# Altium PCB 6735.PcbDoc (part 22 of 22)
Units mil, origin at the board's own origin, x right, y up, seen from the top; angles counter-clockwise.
Board outline 2641.73 x 5165.35 mil, 6 copper layers (Top, Inner Layer 2, Inner Layer 3, Inner Layer 4, Inner Layer 5, Bottom), stack 35.7 mil thick; 1011 components, 790 nets, 4118 pads, 9325 vias.
Unrouted connection lines stored in the file: 4610.
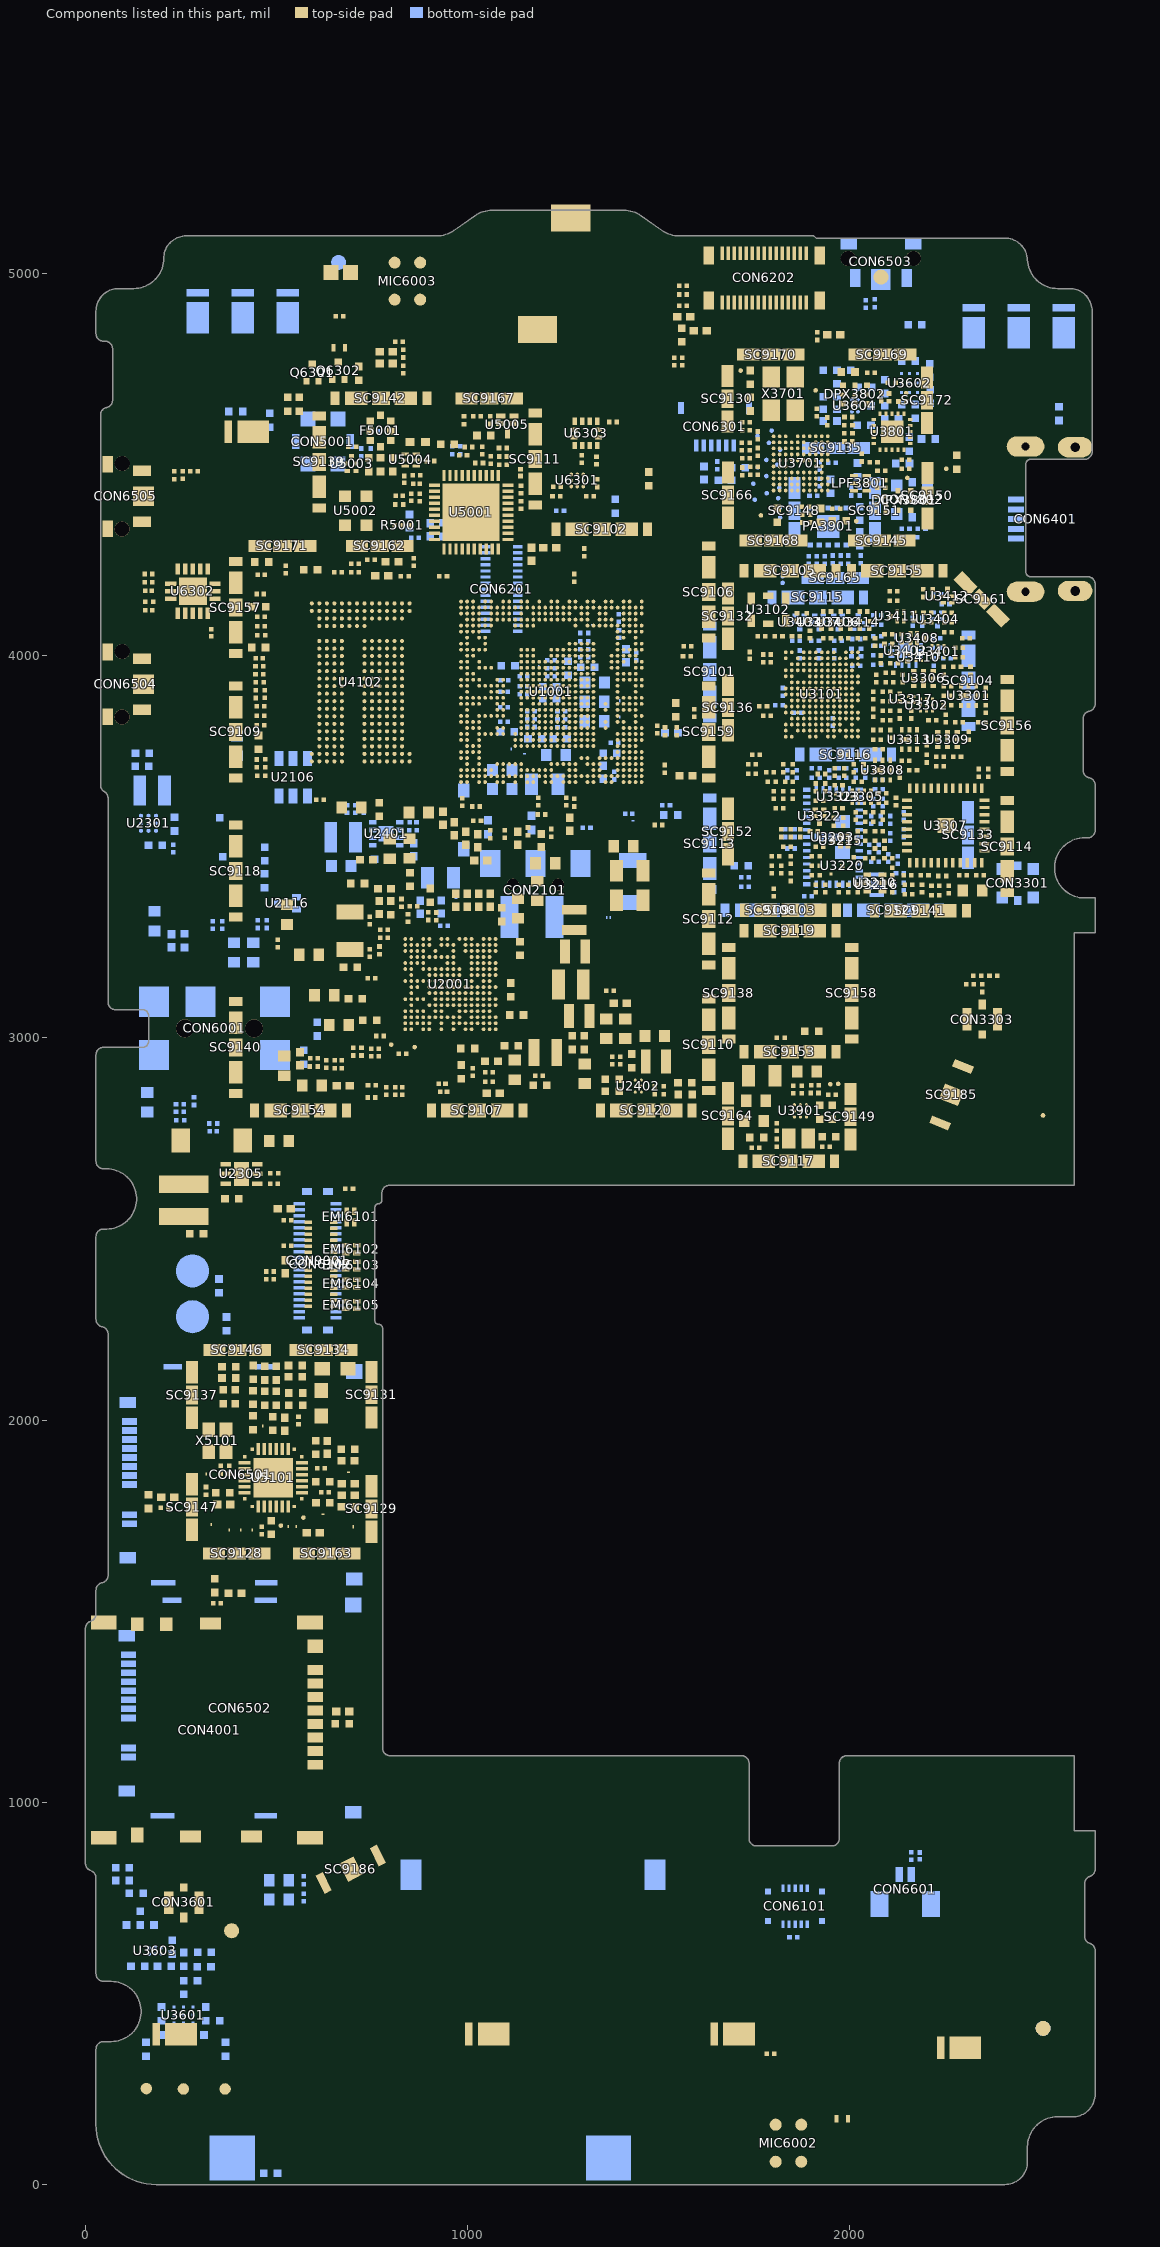
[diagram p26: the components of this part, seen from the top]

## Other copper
Top:
  region net VPA_PMU: 1219.95,2964.49 1283.95,2964.49 1283.95,2922.49 1219.95,2922.49 1219.95,2964.49
  region net D_GND: 1193.95,4655.49 592.95,4655.49 592.95,4691.49 1193.95,4691.49 1193.95,4655.49
  region net VBAT: 1344.95,3020.83 1423.05,3020.83 1440.31,3038.09 1440.31,3070.19 1441.95,3071.83 1449.95,3071.83 1449.95,3022.83 1425.45,2998.33 1344.95,2998.33 1344.95,3020.83
  region net VPROC_PMU: 1302.31,3174.09 1314.31,3174.09 1327.31,3187.09 1327.31,3311.09 1338.56,3322.34 1343.31,3322.34 1343.31,3167.09 1302.31,3167.09 1302.31,3174.09
  region net VBAT_VPROC: 1047.95,3111.83 1049.75,3111.83 1057.95,3104.83 1126.95,3104.83 1129.95,3107.83 1129.95,3119.83 1126.69,3123.09 1095.08,3123.09 1092.82,3121.83 1047.95,3121.83 1047.95,3111.83
  region net D_GND: 2218.65,4803.08 2218.65,4771.49 1694.95,4771.49 1694.95,4316.49 2186.95,4316.49 2186.95,4771.28 2218.95,4771.28 2218.95,4284.49 1664.95,4284.49 1664.95,4803.08 2218.65,4803.08
  region net D_GND: 765.95,2199.49 765.95,2167.49 294.95,2167.49 294.95,1667.49 732.95,1667.49 732.95,2163.49 763.95,2163.49 763.95,1635.49 262.95,1635.49 262.95,2199.49 765.95,2199.49
  region net VBAT_RF: 2302.65,3470.59 2330.65,3470.59 2330.65,3428.59 2302.65,3428.59 2302.65,3470.59
  region net D_GND: 2007.95,2981.56 2007.95,2943.96 1701.95,2943.96 1701.95,2694.96 1985.95,2694.96 1985.95,2940.96 2021.95,2940.96 2021.95,2658.96 1664.95,2658.96 1664.95,2981.56 2007.95,2981.56
  region net D_GND: 1043.08,3854.49 1043.08,3871.49 1049.08,3877.49 1061.95,3877.49 1063.95,3875.49 1063.95,3854.49 1043.08,3854.49
  region net N18393681: 1764.31,2786.56 1833.31,2786.56 1840.31,2793.56 1853.31,2780.56 1843.31,2770.56 1801.81,2770.56 1784.31,2753.06 1784.31,2740.56 1764.31,2740.56 1764.31,2786.56
  region net D_GND: 1100.45,4007.99 1108.95,4016.49 1129.95,4016.49 1134.95,4011.49 1211.95,4011.49 1227.95,4027.49 1241.58,4027.49 1252.33,4038.24 1252.33,4038.49 1257.33,4043.49 1345.58,4043.49 1353.76,4035.3 1359.31,4030.49 1380.95,4030.49 1380.95,4064.49 1378.95,4066.49 1277.95,4066.49 1277.35,4067.09 1143.55,4067.09 1117.55,4041.09 1064.69,4041.09 1087.48,4020.96 1100.45,4007.99
  region net D_GND: 1037.23,3701.49 1044.16,3701.49 1071.16,3728.49 1112.33,3728.49 1116.95,3733.11 1116.95,3765.49 1113.33,3769.11 1059.08,3769.11 1055.08,3765.11 1055.08,3764.62 1041.95,3751.49 1041.95,3711.32 1035,3704.37 1037.23,3701.49
  region net VPA_PMU: 1541.31,2931.09 1569.4,2931.09 1569.4,2904.09 1569.31,2904.09 1569.31,2841.09 1532.31,2841.09 1532.31,2866.09 1504.31,2866.09 1504.31,2896.09 1541.31,2896.09 1541.31,2931.09
  region net VBAT: 1718.31,2936.56 1762.31,2936.56 1762.31,2865.56 1718.31,2865.56 1718.31,2936.56
  region net D_GND: 375.53,2824.17 375.53,4272.09 411.02,4272.09 411.02,2824.17 375.53,2824.17
  pour cut-out: 1135.95,3025.83 1135.95,3049.83 1138.95,3049.83 1138.95,3025.83 1135.95,3025.83
  region net VPROC_PMU: 1270.95,3187.49 1323.71,3187.49 1331.31,3195.09 1331.31,3520.49 1411.31,3520.49 1411.31,3480.13 1434.95,3456.49 1434.95,3361.72 1391.31,3318.09 1391.31,3175.09 1317.31,3101.09 1270.95,3101.09 1270.95,3187.49
  region net D_GND: 1158.95,4312.49 1158.95,4655.49 1194.95,4655.49 1194.95,4312.49 1158.95,4312.49
  region net VSYS_PMU: 959.31,3388.09 1032.31,3388.09 1032.31,3388.83 1072.31,3388.83 1072.31,3358.09 959.31,3358.09 959.31,3388.09
  region net N47514920: 198.31,2557.09 344.31,2557.09 344.31,2629.09 380.31,2629.09 380.31,2532.09 324.31,2532.09 324.31,2477.09 294.31,2477.09 294.31,2510.09 198.31,2510.09 198.31,2557.09
  pour cut-out: 1816.43,3772.94 1820.06,3772.94 1820.06,3767.39 1816.43,3767.39 1816.43,3772.94
  region net D_GND: 1648.02,4312.49 1158.95,4312.49 1158.95,4348.49 1648.02,4348.49 1648.02,4312.49
  region net D_GND: 1079.95,3137.83 1095.95,3153.83 1122.95,3153.83 1122.95,3129.09 1079.95,3129.09 1079.95,3137.83
  region net VBAT: 1279.31,2904.09 1318.31,2904.09 1328.31,2914.09 1373.31,2914.09 1373.31,2877.09 1345.31,2877.09 1317.81,2849.59 1279.31,2849.59 1279.31,2904.09
  region net D_GND: 1041.08,3948.49 1101.08,3948.49 1105.08,3952.49 1105.08,4005.11 1077.08,4033.11 1077.08,4035.49 1071.48,4041.09 1062.68,4041.09 1057.08,4035.49 1057.08,3999.11 1063.08,3993.11 1073.08,3993.11 1079.08,3987.11 1079.08,3969.11 1064.46,3954.49 1041.08,3954.49 1041.08,3948.49
  region net VBAT_RF: 1760.31,2848.56 1770.81,2859.06 1770.81,2931.56 1878.31,2931.56 1878.31,2888.56 1824.31,2888.56 1824.31,2852.56 1791.31,2819.56 1759.31,2819.56 1759.31,2848.56 1760.31,2848.56
  region net VLTE_PMU: 1303.95,3024.83 1303.95,3089.09 1317.21,3089.09 1352.95,3124.83 1359.31,3129.09 1368.31,3129.09 1368.31,3114.45 1375.93,3106.83 1391.31,3106.83 1391.31,3073.83 1347.05,3073.83 1337.95,3064.73 1337.95,3024.83 1303.95,3024.83
  region net D_GND: 1330.27,3744.74 1341.44,3744.49 1392.08,3744.49 1395.84,3748.25 1395.84,3806.41 1381.05,3820.96 1373.74,3820.83 1373.74,3789.41 1368.74,3784.41 1350.75,3784.41 1348.95,3784.83 1348.95,3816.49 1355.95,3823.49 1373.95,3823.49 1373.95,3821.49 1380.67,3821.49 1380.67,3846.49 1356.95,3846.49 1348.95,3854.49 1348.95,3885.49 1340.95,3893.49 1324.95,3893.49 1324.95,3886.49 1335.46,3886.49 1340.95,3881 1340.95,3868.49 1333.95,3861.49 1325.95,3861.49 1325.95,3763.49 1292.95,3763.49 1292.95,3744.74 1330.27,3744.74
  region net DVDD12_EMI: 791.65,3629.49 865.65,3629.49 865.65,3569.49 791.65,3569.49 791.65,3629.49
  region net D_GND: 1720.65,3316.59 1720.65,3352.59 2192.65,3352.59 2192.65,3316.59 1720.65,3316.59
  pour cut-out: 1125.95,3048.83 1135.95,3048.83 1135.95,3046.83 1125.95,3046.83 1125.95,3048.83
  region net VSYS_SW: 1167.95,3268.09 1167.95,3289.49 1190.55,3312.09 1318.31,3312.09 1318.31,3268.99 1229.95,3268.99 1229.05,3268.09 1167.95,3268.09
  region net D_GND: 858.95,4271.49 376.31,4271.49 376.31,4303.49 858.95,4303.49 858.95,4271.49
  region net D_GND: 1648.95,2791.49 376.36,2791.49 376.36,2827.49 1648.95,2827.49 1648.95,2791.49
  region net VPROC_SW: 1126.82,3177.99 1170.95,3177.99 1174.2,3178.09 1262.31,3178.09 1262.31,3101.09 1219.95,3101.09 1219.95,3138.49 1212.61,3145.83 1141.59,3145.83 1126.82,3160.57 1126.82,3177.99
  region net VBAT_RF: 2297.65,3438.59 2338.65,3438.59 2338.65,3416.59 2342.65,3412.59 2364.65,3412.59 2364.65,3364.53 2315.65,3364.53 2315.65,3404.59 2311.65,3408.59 2297.65,3408.59 2297.65,3438.59
  region net DVDD_LTE: 1397.31,3077.09 1397.31,3137.09 1434.31,3137.09 1434.31,3077.09 1397.31,3077.09
  region net VBAT: 1345.31,3016.09 1422.21,3016.09 1440.31,3034.19 1440.31,3163.09 1488.31,3163.09 1488.31,3067.09 1473.81,3052.59 1473.81,2977.09 1345.31,2977.09 1345.31,3016.09
  region net VM_EXT: 644.2,3629.49 697.95,3629.49 697.95,3618.49 687.45,3607.99 652.95,3607.99 644.2,3616.74 644.2,3629.49
  region net N19717773: 884.95,96.83 1204.95,12.83 1427.95,12.83 1427.95,135.83 884.95,135.83 884.95,96.83
  region net D_GND: 1156.95,3733.49 1177.95,3712.49 1197.95,3712.49 1213.45,3727.99 1213.45,3735.49 1212.2,3736.74 1156.95,3736.74 1156.95,3733.49
  region net D_GND: 1664.95,3315.64 1664.95,4240.04 1696.95,4240.04 1696.95,3315.64 1664.95,3315.64
  pour cut-out: 1766.31,4763.09 1886.31,4763.09 1886.31,4611.99 1766.31,4611.99 1766.31,4763.09
  region net VCC2_PA: 1943.31,2797.56 1965.31,2797.56 1977.31,2785.56 1977.31,2730.56 1951.31,2730.56 1951.31,2757.56 1943.31,2765.56 1943.31,2797.56
  region net VPA_VCC2: 1937.31,3002.56 1957.31,3022.56 1957.31,3042.56 1977.31,3042.56 1977.31,3007.56 1958.81,2989.06 1937.31,2989.06 1937.31,3002.56
  region net DVDD12_EMI: 704.95,3622.49 725.95,3622.49 748.95,3599.49 816.95,3599.49 824.95,3607.49 865.95,3607.49 865.95,3569.49 802.95,3569.49 789.95,3556.49 756.95,3556.49 731.95,3581.49 704.95,3581.49 704.95,3622.49
  region net VBAT_VPROC: 1348.95,3065.83 1384.95,3065.83 1384.95,3035.83 1348.95,3035.83 1348.95,3065.83
  region net VCORE_SW: 1158.95,3205.49 1199.95,3205.49 1234.7,3240.24 1234.7,3259.99 1273.45,3259.99 1273.45,3198.49 1261.05,3186.09 1158.95,3186.09 1158.95,3205.49
  pour cut-out: 231.31,765.09 285.31,765.09 285.31,711.09 231.31,711.09 231.31,765.09
  region net VBAT: 1448.31,3162.09 1487.31,3162.09 1487.31,3072.09 1448.31,3072.09 1448.31,3162.09
  region net DVDD12_EMI: 729.08,3755.11 696.33,3755.11 665.08,3786.36 665.08,3974.62 697.57,4007.11 733.08,4007.11 737.08,4003.11 737.08,3994.62 733.95,3991.49 724.95,3991.49 717.95,3984.49 717.95,3775.49 722.95,3770.49 730.95,3770.49 735.08,3766.36 735.08,3761.11 729.08,3755.11
  region net VPA_SW: 1154.31,2925.09 1154.31,2990.09 1145.81,2998.59 1103.31,2998.59 1084.06,3017.84 1084.06,3033.09 1103.31,3033.09 1110.81,3025.59 1164.31,3025.59 1187.31,3003.09 1187.31,2925.09 1154.31,2925.09
  region net D_GND: 1612.95,2818.49 1612.95,4345.49 1648.14,4345.49 1648.14,2818.49 1612.95,2818.49
  region net D_GND: 592.95,4311.49 592.95,4653.49 628.95,4653.49 628.95,4311.49 592.95,4311.49
  region net D_GND: 2421.45,3315.25 1664.95,3315.25 1664.95,3350.96 2421.45,3350.96 2421.45,3315.25
  region net VPA_VCC2: 1578.31,2865.09 1605.31,2865.09 1605.31,2839.09 1578.31,2839.09 1578.31,2865.09
  pour cut-out: 630.93,4463.11 803.08,4463.11 803.08,4300.11 630.93,4300.11 630.93,4463.11
  pour cut-out: 895.95,4454.49 931.95,4454.49 931.95,4438.49 895.95,4438.49 895.95,4454.49
  region net D_GND: 1694.95,4239.87 2275.18,4239.87 2428.15,4086.66 2428.15,4065.49 2404.95,4065.49 2265.95,4204.49 1694.95,4204.49 1694.95,4239.87
  region net N47514918: 225.31,2594.09 225.31,2765.09 280.31,2765.09 280.31,2691.09 381.31,2691.09 381.31,2664.09 328.31,2664.09 328.31,2594.09 225.31,2594.09
  region net D_GND: 1039.08,3806.49 1039.08,3830.71 1101.35,3830.71 1108.95,3823.11 1108.95,3806.49 1039.08,3806.49
  region net VPROC_PMU: 1360.95,3578.83 1386.95,3578.83 1386.95,3495.83 1360.95,3495.83 1360.95,3578.83
  pour cut-out: 1727.56,4177.5 1845.06,4177.5 1845.06,4067.5 1727.56,4067.5 1727.56,4177.5
  region net VLTE_SW: 1171.95,3097.49 1192.95,3097.49 1196.45,3093.99 1261.95,3093.99 1266.2,3094.09 1279.31,3094.09 1279.31,3025.49 1248.95,3025.49 1248.95,3042.49 1239.45,3051.99 1171.95,3051.99 1171.95,3097.49
  region net D_GND: 2021.95,3298.96 2021.95,3262.96 1701.95,3262.96 1701.95,2978.96 1985.95,2978.96 1985.95,3259.96 2022.67,3259.96 2022.67,2942.96 1664.95,2942.96 1664.95,3298.96 2021.95,3298.96
  region net VBAT_VSYS: 1079.31,3283.49 1079.31,3314.85 1083.55,3319.09 1100.05,3319.09 1119.05,3338.09 1186.45,3338.09 1186.45,3317.49 1161.45,3292.49 1107.45,3292.49 1103.2,3288.24 1103.2,3277.99 1087.32,3262.11 1058.95,3262.11 1077.89,3281.05 1077.89,3283.49 1079.31,3283.49
  region net VPROC_PMU: 1330.95,3516.49 1330.95,3520.49 1363.45,3552.99 1385.95,3552.99 1411.31,3527.63 1411.31,3516.49 1330.95,3516.49
  region net D_GND: 1000.95,3729.49 1010.95,3719.49 1014.95,3719.49 1024.7,3729.24 1031.95,3729.24 1033.58,3730.87 1033.58,3733.49 1031.26,3735.8 1025.95,3735.8 1016.61,3745.15 1012.61,3745.15 1000.95,3733.49 1000.95,3729.49
  region net D_GND: 2393.45,3316.85 2393.45,4092.99 2421.78,4092.99 2428.72,4086.05 2428.72,3316.85 2393.45,3316.85
  region net VBAT_VCORE: 1159.45,3258.49 1197.45,3258.49 1197.45,3219.99 1159.45,3219.99 1159.45,3258.49
  region net VBAT_RF_CDMA: 1708.31,2749.56 1708.31,2784.56 1738.31,2784.56 1745.31,2777.56 1753.31,2777.56 1753.31,2761.56 1720.31,2761.56 1720.31,2749.56 1708.31,2749.56
Inner Layer 2:
  region net VCC2_PA: 1947.31,2794.56 2013.31,2794.56 2013.31,2760.56 1947.31,2760.56 1947.31,2794.56
  pour cut-out: 1069.95,2954.83 1069.95,2905.83 1050.95,2886.83 1019.95,2886.83 1019.95,2882.09 1053.31,2882.09 1074.31,2903.09 1074.31,2954.83 1069.95,2954.83
  pour cut-out: 1963.75,3066.25 1983.75,3046.25 1987.5,3050 1967.5,3070 1963.75,3066.25
  pour cut-out: 1793.87,4580.65 1803.42,4590.2 1803.42,4612.09 1766.31,4612.09 1766.31,4763.11 1886.31,4763.11 1886.31,4611.88 1847.1,4611.88 1822.85,4587.63 1822.85,4568.19 1793.87,4568.19 1793.87,4580.65
  region net D_GND: 1117.95,3348.83 1135.95,3348.83 1135.95,3315.83 1117.95,3315.83 1117.95,3348.83
  pour cut-out: 852.31,4537.09 889.31,4537.09 905.81,4520.59 934.31,4520.59 962.06,4492.84 962.06,4453.09 944.31,4453.09 944.31,4482.09 928.81,4497.59 883.31,4497.59 881.56,4499.34 881.56,4516.09 876.94,4520.72 852.31,4520.72 852.31,4537.09
  region net VPA_PMU: 1519.95,2926.09 1556.95,2926.09 1556.95,2859.49 1519.95,2859.49 1519.95,2926.09
  region net VBAT: 1728.31,2870.06 1728.31,2935.5 1735.31,2942.5 1761.31,2942.5 1761.31,2877.56 1753.81,2870.06 1728.31,2870.06
  pour cut-out: 1521.31,3203.09 1560.31,3203.09 1560.31,3181.09 1521.31,3181.09 1521.31,3203.09
  pour cut-out: 2319.95,3073.83 2373.95,3073.83 2373.95,3018.83 2319.95,3018.83 2319.95,3073.83
  region net VCORE_PMU: 1214.95,3751.1 1214.95,3827.47 1219.08,3831.6 1235.08,3831.6 1239.95,3826.73 1239.95,3751.1 1214.95,3751.1
  region net VCORE_PMU: 1142.95,3764.48 1134.08,3773.35 1134.08,3842.61 1136.95,3845.48 1148.95,3845.48 1160.95,3833.48 1160.95,3764.48 1142.95,3764.48
  pour cut-out: 782.63,4603.09 807.31,4603.09 809.81,4605.59 974.31,4605.59 1022.56,4557.34 1046.31,4557.34 1049.94,4553.72 1049.94,4494.09 1041.13,4485.28 1041.13,4455.09 1023.31,4455.09 1023.31,4494.09 1029.81,4500.59 1029.81,4534.09 1009.31,4534.09 1000.31,4543.09 1000.31,4551.09 966.81,4584.59 816.31,4584.59 815.06,4583.34 815.06,4577.09 809.69,4571.72 786.31,4571.72 782.63,4575.4 782.63,4603.09
  pour cut-out: 241.31,714.09 273.31,714.09 273.31,682.09 241.31,682.09 241.31,714.09
  pour cut-out: 949.2,4420.24 958.45,4410.99 939.45,4391.99 939.45,4349.49 974.2,4314.74 974.2,4294.49 957.95,4294.49 957.95,4315.49 926.45,4346.99 926.45,4397.49 949.2,4420.24
  region net VCORE_PMU: 1293.95,3273.49 1431.31,3273.49 1431.31,3203.49 1293.95,3203.49 1293.95,3273.49
  region net VPROC_PMU: 1166.95,3837.6 1180.58,3837.6 1183.58,3840.6 1192.58,3840.6 1195.58,3837.6 1237.58,3837.6 1239.95,3839.97 1239.95,3973.23 1236.08,3977.1 1227.57,3977.1 1216.95,3966.48 1216.95,3872.47 1207.58,3863.1 1182.08,3863.1 1176.95,3868.23 1176.95,3970.23 1173.08,3974.1 1153.58,3974.1 1150.58,3971.1 1150.58,3856.85 1166.95,3840.48 1166.95,3837.6
  pour cut-out: 733.31,4603.09 761.31,4603.09 761.31,4572.09 733.31,4572.09 733.31,4603.09
  pour cut-out: 1069.31,4455.09 1069.31,4534.09 1090.31,4534.09 1090.31,4599.09 1115.31,4599.09 1115.31,4512.09 1093.31,4512.09 1093.31,4490.09 1089.81,4486.59 1089.81,4455.09 1069.31,4455.09
  region net VBAT_VPROC: 1158.95,3099.83 1158.95,3123.83 1288.95,3123.83 1340.95,3071.83 1384.95,3071.83 1384.95,3036.83 1262.95,3036.83 1199.95,3099.83 1158.95,3099.83
  region net D_GND: 1126.95,3233.83 1126.95,3258.83 1146.95,3258.83 1146.95,3233.83 1126.95,3233.83
  pour cut-out: 1117.31,2997.83 1122.95,2997.83 1122.95,2977.83 1131.95,2968.83 1190.95,2968.83 1190.95,2964.09 1127.31,2964.09 1117.31,2974.09 1117.31,2997.83
  region net DVDD_LTE: 1399.31,3197.09 1445.31,3197.09 1445.31,3112.09 1399.31,3112.09 1399.31,3197.09
  region net VPROC_PMU: 1359.95,3498.83 1359.95,3594.83 1391.95,3594.83 1403.45,3583.33 1403.45,3498.83 1359.95,3498.83
  region net VPA_VCC2: 1582.31,2880.09 1613.31,2880.09 1613.31,2841.09 1582.31,2841.09 1582.31,2880.09
  region net VBAT: 1684.31,2846.56 1727.31,2889.56 1761.31,2889.56 1761.31,2856.56 1734.31,2829.56 1684.31,2829.56 1684.31,2846.56
  region net VPA_PMU: 1252.95,2947.49 1289.95,2947.49 1289.95,2897.49 1252.95,2897.49 1252.95,2947.49
  region net VM_EXT: 645.95,3635.49 730.95,3635.49 730.95,3620.09 645.95,3620.09 645.95,3635.49
  pour cut-out: 1727.56,4177.5 1845.06,4177.5 1845.06,4067.5 1727.56,4067.5 1727.56,4177.5
  region net D_GND: 1019.82,3105.09 1051.69,3105.09 1057.69,3099.09 1141.69,3099.09 1167.95,3072.83 1167.95,3057.83 1142.95,3057.83 1142.95,3069.83 1132.45,3080.33 1058.95,3080.33 1052.7,3086.58 1026.95,3086.58 1019.82,3093.7 1019.82,3105.09
  pour cut-out: 1144.95,3025.83 1169.95,3025.83 1169.95,3077.83 1176.31,3077.83 1176.31,3021.09 1144.95,3021.09 1144.95,3025.83
  region net VBAT_VLTE: 1296.31,2948.09 1330.31,2948.09 1330.31,2910.09 1296.31,2910.09 1296.31,2948.09
  region net VBAT_RF: 1839.31,2887.56 1839.31,2923.56 1869.81,2954.06 1933.31,2954.06 1933.31,2893.56 1888.31,2893.56 1882.31,2887.56 1839.31,2887.56
  region net DVDD12_EMI: 791.95,3635.49 918.31,3635.49 918.31,3618.09 791.95,3618.09 791.95,3635.49
  pour cut-out: 630.92,4463.11 803.08,4463.11 803.08,4300.11 630.92,4300.11 630.92,4463.11
  pour cut-out: 1084.95,3258.83 1084.95,3334.83 1105.21,3355.09 1142.31,3355.09 1142.31,3318.09 1119.45,3295.23 1119.45,3243.83 1114.95,3243.83 1114.95,3310.83 1127.95,3323.83 1127.95,3344.83 1099.95,3344.83 1089.95,3334.83 1089.95,3258.83 1084.95,3258.83
  pour cut-out: 1014.95,3170.83 1014.95,3190.83 1078.95,3190.83 1123.95,3235.83 1123.95,3274.09 1181.31,3274.09 1181.31,3226.09 1150.95,3226.09 1150.95,3225.83 1095.95,3170.83 1014.95,3170.83
  pour cut-out: 2330.31,3106.09 2362.31,3106.09 2362.31,3074.09 2330.31,3074.09 2330.31,3106.09
  pour cut-out: 1724.15,3683.81 1722.53,3686.24 1721.55,3691.16 1722.53,3696.08 1725.32,3700.25 1729.49,3703.04 1734.41,3704.02 1739.33,3703.04 1743.5,3700.25 1746.29,3696.08 1747.27,3691.16 1746.29,3686.24 1744.65,3683.8 1744.66,3683.81 1744.43,3386.61 1744.4,3386.41 1745.4,3378.87 1748.3,3371.85 1752.93,3365.81 1754.03,3364.98 1754.1,3365.04 1763.6,3355.54 1765.88,3354.82 1769.63,3355.65 1771.52,3356.03 1778.2,3354.7 1783.87,3350.91 1787.65,3345.25 1788.98,3338.56 1787.65,3331.88 1783.87,3326.22 1778.2,3322.43 1771.52,3321.1 1764.84,3322.43 1759.17,3326.22 1755.39,3331.88 1754.65,3335.59 1737.67,3352.56 1734.26,3356.72 1728.49,3367.51 1724.93,3379.23 1724.12,3387.5 1724.15,3387.59 1724.16,3683.81
  region net VBAT: 1452.95,3097.49 1452.95,3197.47 1446.45,3203.97 1446.45,3274.49 1497.95,3274.49 1497.95,3182.49 1506.95,3173.49 1506.95,3097.49 1452.95,3097.49
  region net VMCH_PMU: 481.31,3074.09 465.31,3090.09 532.81,3157.59 532.81,3175.09 542.31,3175.09 556.31,3161.09 556.31,3149.09 481.31,3074.09
  region net VBAT_RF_CDMA: 1931.31,2812.56 1952.31,2833.56 1958.31,2833.56 1979.31,2812.56 1979.31,2803.56 1933.31,2803.56 1933.31,2812.56 1931.31,2812.56
  region net VBAT_RF_CDMA: 1708.31,2771.56 1757.31,2771.56 1757.31,2745.56 1708.31,2745.56 1708.31,2771.56
  pour cut-out: 1962.65,3811.59 1967.65,3811.59 1967.65,3830.59 1867.65,3830.59 1867.65,3811.59 1871.65,3807.59 1873.65,3807.59 1873.65,3794.59 1879.65,3794.59 1879.65,3814.59 1873.65,3814.59 1873.65,3824.59 1962.65,3824.59 1962.65,3811.59
  pour cut-out: 654.31,3347.09 732.31,3347.09 732.31,3201.09 654.31,3201.09 654.31,3347.09
  region net D_GND: 1127.95,3263.09 1155.21,3263.09 1161.45,3269.33 1168.31,3269.33 1168.31,3244.19 1158.45,3234.33 1127.95,3234.33 1127.95,3263.09
  pour cut-out: 755.92,4645.09 784.31,4645.09 787.31,4642.09 996.31,4642.09 999.81,4638.59 1104.31,4638.59 1106.56,4636.34 1106.56,4616.09 1105.44,4614.97 1104.44,4613.97 981.31,4613.97 974.75,4620.53 790.31,4620.53 784.09,4614.31 758.31,4614.31 755.92,4616.7 755.92,4645.09
  region net D_GND: 1087.95,3331.83 1100.95,3344.83 1126.95,3344.83 1126.95,3323.83 1087.95,3323.83 1087.95,3331.83
  region net VBAT_VLTE: 1062.05,3073.83 1060.45,3071.33 1060.45,3064.83 1064.2,3061.08 1091.82,3061.08 1099.08,3053.83 1133.33,3053.83 1135.95,3056.45 1135.95,3065.52 1127.64,3073.83 1062.05,3073.83
  region net VBAT_VCORE: 1173.95,3244.83 1207.57,3244.83 1277.57,3174.83 1317.57,3174.83 1376.57,3115.83 1386.57,3115.83 1420.95,3081.45 1420.95,3037.83 1394.95,3037.83 1394.95,3070.83 1384.95,3080.83 1370.45,3080.83 1310.2,3141.08 1263.32,3141.08 1186.95,3217.46 1173.95,3217.46 1173.95,3244.83
  pour cut-out: 231.31,766.09 285.31,766.09 285.31,711.09 231.31,711.09 231.31,766.09
  pour cut-out: 923.31,3092.09 923.79,3092.73 923.79,3121.54 949.31,3121.54 949.31,3096.09 942.31,3089.09 942.31,3079.09 923.31,3079.09 923.31,3092.09
  region net VBAT_VPROC: 1023.31,3111.58 1023.31,3122.83 1143.95,3122.83 1145.45,3124.33 1170.95,3124.33 1170.95,3100.09 1150.31,3100.09 1145.31,3105.09 1066.31,3105.09 1059.82,3111.58 1023.31,3111.58
  region net VPROC_SW: 1019.95,3169.09 1098.21,3169.09 1109.95,3180.83 1208.31,3180.83 1208.31,3150.83 1080.95,3150.83 1076.95,3146.83 1059.95,3146.83 1048.45,3158.33 1019.95,3158.33 1019.95,3169.09
  pour cut-out: 2319.95,3073.83 2373.95,3073.83 2373.95,3018.83 2319.95,3018.83 2319.95,3073.83
  pour cut-out: 682.06,4510.09 707.31,4510.09 710.31,4513.09 710.31,4533.09 757.31,4533.09 757.31,4498.09 698.31,4498.09 693.81,4493.59 693.81,4475.09 698.56,4470.34 723.31,4470.34 726.94,4466.72 784.31,4466.72 789,4471.4 789,4502.09 849.31,4502.09 849.31,4522.09 820.31,4522.09 809.31,4533.09 787.31,4533.09 787.31,4559.09 782.31,4564.09 760.31,4564.09 751.31,4555.09 721.31,4555.09 715.31,4561.09 682.31,4561.09 674.81,4553.59 674.81,4527.09 682.06,4519.84 682.06,4510.09
  pour cut-out: 873.95,4474.84 931.95,4474.84 931.95,4438.49 873.95,4438.49 873.95,4474.84
  region net VLTE_SRAM: 1373.95,3197.09 1393.31,3197.09 1393.31,3131.09 1373.95,3131.09 1373.95,3197.09
  region net DVDD12_EMI: 672.08,3702.11 731.08,3702.11 738.08,3709.11 738.08,3727.11 734.08,3731.11 726.08,3731.11 712.08,3745.11 712.08,3833.11 698.08,3847.11 698.08,3917.11 712.08,3931.11 739.08,3931.11 744.08,3936.11 744.08,3949.11 728.08,3965.11 706.08,3965.11 698.08,3973.11 698.08,4003.11 724.08,4029.11 734.08,4029.11 740.08,4035.11 740.08,4043.11 730.08,4053.11 670.08,4053.11 662.08,4045.11 662.08,3781.11 668.08,3775.11 676.08,3775.11 682.08,3769.11 682.08,3759.11 664.95,3741.98 664.95,3709.24 672.08,3702.11
  region net VPA_PMU: 1235.31,2947.09 1285.31,2947.09 1285.31,2921.09 1235.31,2921.09 1235.31,2947.09
  region net DVDD_LTE: 1275.08,3900.48 1269.08,3906.48 1269.08,3985.1 1261.08,3993.1 1261.08,4033.1 1265.08,4037.1 1311.5,4037.1 1317.5,4031.1 1317.5,3904.48 1313.5,3900.48 1275.08,3900.48
  pour cut-out: 970.76,4422.49 ccw(c957.95,4422.49) 957.95,4435.3 ccw(c957.95,4422.49) 945.14,4422.49 ccw(c957.95,4422.49) 957.95,4409.68 ccw(c957.95,4422.49)
Inner Layer 3:
  pour cut-out: 759.95,4428.49 958.95,4428.49 958.95,4414.1 759.95,4414.1 759.95,4428.49
  pour cut-out: 653.95,4433.61 750.77,4433.61 750.77,4325.61 662.77,4325.61 662.77,4432.61 653.95,4432.61 653.95,4316.49 759.95,4316.49 759.95,4444.49 653.95,4444.49 653.95,4433.61
  pour cut-out: 1724.15,3683.81 1722.53,3686.24 1721.55,3691.16 1722.53,3696.08 1725.32,3700.25 1729.49,3703.04 1734.41,3704.02 1739.33,3703.04 1743.5,3700.25 1746.29,3696.08 1747.27,3691.16 1746.29,3686.24 1744.65,3683.8 1744.66,3683.81 1744.43,3386.61 1744.4,3386.41 1745.4,3378.87 1748.3,3371.85 1752.93,3365.81 1754.03,3364.98 1754.1,3365.04 1763.6,3355.54 1765.88,3354.82 1769.63,3355.65 1771.52,3356.03 1778.2,3354.7 1783.87,3350.91 1787.65,3345.25 1788.98,3338.56 1787.65,3331.88 1783.87,3326.22 1778.2,3322.43 1771.52,3321.1 1764.84,3322.43 1759.17,3326.22 1755.39,3331.88 1754.65,3335.59 1737.67,3352.56 1734.26,3356.72 1728.49,3367.51 1724.93,3379.23 1724.12,3387.5 1724.15,3387.59 1724.16,3683.81
  pour cut-out: 970.76,4422.49 ccw(c957.95,4422.49) 957.95,4435.3 ccw(c957.95,4422.49) 945.14,4422.49 ccw(c957.95,4422.49) 957.95,4409.68 ccw(c957.95,4422.49)
  pour cut-out: 970.76,4422.49 ccw(c957.95,4422.49) 957.95,4435.3 ccw(c957.95,4422.49) 945.14,4422.49 ccw(c957.95,4422.49) 957.95,4409.68 ccw(c957.95,4422.49)
Inner Layer 4:
  region net VPROC_PMU: 1225.95,3893.49 1220.95,3898.49 1220.95,3970.49 1225.95,3975.49 1236.95,3975.49 1241.95,3970.49 1241.95,3898.49 1236.95,3893.49 1225.95,3893.49
  pour cut-out: 1946.56,3737.83 1952.21,3742.17 1958.8,3744.89 1965.86,3745.82 1965.86,3745.59 2106.65,3745.57 2108.2,3743.25 2113.86,3739.47 2120.54,3738.14 2127.22,3739.47 2132.88,3743.25 2136.66,3748.91 2137.99,3755.59 2136.66,3762.27 2132.88,3767.93 2127.22,3771.71 2120.54,3773.04 2113.86,3771.71 2108.2,3767.93 2106.63,3765.58 2106.65,3765.59 1964.41,3765.96 1953.22,3764.49 1942.79,3760.17 1933.84,3753.3 1934.1,3753.04 1900.65,3719.85 1895.25,3718.78 1890.64,3715.7 1887.55,3711.08 1886.47,3705.64 1887.55,3700.19 1890.64,3695.58 1895.25,3692.49 1900.7,3691.41 1906.14,3692.49 1910.76,3695.58 1913.84,3700.19 1914.92,3705.59 1914.65,3705.59 1946.73,3737.66
  pour cut-out: 1932.65,3444.59 2014.48,3444.43 2018.9,3441.48 2024.33,3440.4 2029.76,3441.48 2034.36,3444.56 2037.43,3449.16 2038.51,3454.59 2037.43,3460.02 2034.36,3464.62 2029.76,3467.7 2024.33,3468.78 2018.9,3467.7 2014.5,3464.76 2014.65,3464.59 1925.67,3464.59 1923.15,3466.27 1916.47,3467.6 1909.79,3466.27 1904.13,3462.49 1900.35,3456.83 1899.02,3450.15 1900.35,3443.47 1904.13,3437.81 1909.79,3434.03 1916.47,3432.7 1923.15,3434.03 1928.81,3437.81 1932.59,3443.47 1932.8,3444.53 1932.65,3444.59
  pour cut-out: 2175.13,3686.38 2182.41,3687.34 2189.2,3690.15 2195.02,3694.62 2194.85,3694.79 2288.05,3787.62 2292.86,3793.89 2295.88,3801.18 2296.91,3809.02 2296.65,3809.02 2296.24,3838.52 2297.83,3842.35 2298.12,3842.05 2298.64,3842.59 2301.56,3842.01 2308.26,3843.34 2313.93,3847.13 2317.72,3852.8 2319.06,3859.5 2317.72,3866.19 2313.93,3871.87 2308.26,3875.66 2301.56,3876.99 2294.87,3875.66 2289.19,3871.87 2285.4,3866.19 2284.07,3859.5 2284.64,3856.61 2284.65,3856.59 2282.87,3855.42 2277.94,3848.05 2276.22,3839.37 2276.65,3839.37 2276.96,3811.11 2275.74,3804.97 2272.26,3799.76 2272.04,3799.98 2184.79,3712.17 2178.17,3707.75 2170.37,3706.2 2170.37,3706.59 2098.82,3706.67 2095.98,3710.92 2091.29,3714.05 2085.76,3715.15 2080.23,3714.05 2075.54,3710.92 2072.41,3706.23 2071.31,3700.7 2072.41,3695.17 2075.54,3690.48 2080.23,3687.35 2085.76,3686.25 2089.78,3687.04 2089.76,3687.1 2093.09,3686.62 2175.13,3686.62
  region net D_GND: 1197.95,3880.49 1192.95,3885.49 1192.95,3957.49 1197.95,3962.49 1208.95,3962.49 1213.95,3957.49 1213.95,3885.49 1208.95,3880.49 1197.95,3880.49
  pour cut-out: 1836.24,3308.07 1837.58,3307.17 1841.48,3306.39 1841.48,3306.59 2146.12,3306.59 2151.47,3309.62 2152.65,3311.59 2184.65,3343.59 2188.65,3349.59 2190.65,3357.59 2190.25,3445.62 2191.86,3457.88 2196.6,3469.31 2204.12,3479.12 2213.94,3486.65 2225.36,3491.38 2237.63,3493 2237.63,3492.59 2292.08,3492.24 2302.53,3493.62 2312.26,3497.65 2320.61,3504.06 2320.37,3504.31 2378.65,3562.59 2378.64,3567.59 2376.29,3569.16 2372.5,3574.83 2371.17,3581.52 2372.5,3588.22 2376.29,3593.89 2381.96,3597.68 2388.65,3599.01 2395.34,3597.68 2401.02,3593.89 2404.81,3588.22 2406.14,3581.52 2404.81,3574.83 2401.02,3569.16 2398.64,3567.57 2398.65,3567.59 2398.65,3554.59 2336.5,3491.98 2326.3,3483.61 2314.66,3477.39 2302.04,3473.56 2288.91,3472.27 2288.91,3472.59 2237.85,3472.82 2230.75,3471.89 2224.13,3469.15 2218.45,3464.79 2214.09,3459.11 2211.35,3452.49 2210.42,3445.39 2210.65,3445.39 2211,3358.16 2209.62,3347.72 2205.59,3337.99 2199.18,3329.63 2198.94,3329.87 2168.45,3299.38 2165.48,3295.51 2158.72,3290.32 2150.85,3287.06 2147.24,3286.59 2147.23,3286.59 1829.31,3286.32 1823.98,3287.38 1819.46,3290.4 1819.65,3290.59 1784.65,3325.59 1782.7,3325.53 1778.57,3322.76 1772.06,3321.47 1765.54,3322.76 1760.02,3326.45 1756.33,3331.98 1755.04,3338.49 1756.33,3345 1760.02,3350.52 1765.54,3354.21 1772.06,3355.51 1778.57,3354.21 1784.09,3350.52 1786.71,3346.61 1786.65,3346.59 1794.65,3342.59 1797.65,3340.59 1804.65,3334.59 1822.65,3316.59 1825.65,3314.59 1836.24,3308.07
  pour cut-out: 1994.27,3723.83 2005.02,3732.08 2017.53,3737.27 2030.97,3739.03 2030.97,3738.59 2097.51,3738.79 2101.41,3738.01 2104.72,3735.8 2104.58,3735.66 2106.59,3733.38 2109.89,3731.17 2113.79,3730.39 2113.79,3730.59 2155.04,3730.37 2159.39,3731.24 2163.07,3733.7 2162.91,3733.85 2199.07,3769.46 2203.49,3776.07 2205.04,3783.87 2204.65,3783.87 2204.64,3784.59 2202.23,3786.2 2198.42,3791.9 2197.08,3798.62 2198.42,3805.35 2202.23,3811.04 2207.93,3814.85 2214.65,3816.19 2221.38,3814.85 2227.08,3811.04 2230.88,3805.35 2232.22,3798.62 2230.88,3791.9 2227.08,3786.2 2224.66,3784.59 2224.65,3784.59 2225,3784.03 2223.63,3773.67 2219.63,3764.01 2213.27,3755.72 2213.03,3755.96 2176.04,3718.64 2170.18,3714.14 2163.35,3711.31 2156.03,3710.35 2156.03,3710.59 2103.07,3710.31 2100.45,3711.39 2100.65,3711.59 2097.07,3715.48 2093.39,3717.94 2089.04,3718.81 2089.04,3718.59 2030.08,3718.85 2022.25,3717.82 2014.95,3714.8 2008.68,3709.99 2008.87,3709.8 2004.92,3705.58 2004.93,3705.53 2003.84,3700.05 2000.73,3695.4 1996.08,3692.29 1990.59,3691.2 1985.11,3692.29 1980.46,3695.4 1977.35,3700.05 1976.26,3705.53 1977.35,3711.02 1980.46,3715.67 1985.11,3718.77 1990.59,3719.87 1990.67,3719.85 1990.65,3719.59 1994.58,3723.52
  region net VPROC_PMU: 1225.95,3893.49 1220.95,3898.49 1220.95,3970.49 1225.95,3975.49 1236.95,3975.49 1241.95,3970.49 1241.95,3898.49 1236.95,3893.49 1225.95,3893.49
  region net D_GND: 1197.95,3880.49 1192.95,3885.49 1192.95,3957.49 1197.95,3962.49 1208.95,3962.49 1213.95,3957.49 1213.95,3885.49 1208.95,3880.49 1197.95,3880.49
  region net VPROC_PMU: 1151.95,3896.49 1146.95,3901.49 1146.95,3973.49 1151.95,3978.49 1162.95,3978.49 1167.95,3973.49 1167.95,3901.49 1162.95,3896.49 1151.95,3896.49
  pour cut-out: 1870.65,3360.59 2125.49,3360.67 2128.93,3365.82 2134.99,3369.86 2142.12,3371.28 2149.26,3369.86 2152.65,3367.6 2154.27,3370.03 2159.95,3373.82 2166.65,3375.15 2173.35,3373.82 2179.03,3370.03 2182.83,3364.35 2184.16,3357.65 2182.83,3350.95 2179.03,3345.26 2177.03,3343.93 2177.01,3343.95 2158.52,3325.46 2157.65,3324.59 1856.07,3324.59 1852.46,3325.06 1844.59,3328.32 1837.83,3333.51 1834.85,3337.38 1834.87,3337.38 1830.17,3342.04 1828.12,3341.63 1821.27,3342.99 1815.47,3346.87 1811.59,3352.67 1810.23,3359.51 1811.59,3366.36 1815.47,3372.16 1820.7,3375.65 1820.79,3375.45 1816.65,3379.59 1791.52,3379.59 1792.04,3376.97 1790.72,3370.29 1786.93,3364.64 1781.28,3360.85 1774.6,3359.53 1767.93,3360.85 1762.27,3364.64 1758.49,3370.29 1757.16,3376.97 1758.49,3383.64 1762.27,3389.3 1767.93,3393.08 1774.6,3394.41 1778.66,3393.61 1778.47,3393.76 1778.65,3394 1785.65,3399.37 1793.79,3402.74 1801.65,3403.77 1801.65,3403.59 1817.64,3403.73 1823.79,3402.92 1830.17,3400.28 1835.65,3396.08 1837.16,3394.11 1837.15,3394.09 1870.65,3360.59
  region net VPA_PMU: 1509.31,2922.09 1560.31,2922.09 1560.31,2893.09 1509.31,2893.09 1509.31,2922.09
  pour cut-out: 2115.46,3465.39 2112.33,3470.07 2111.23,3475.59 2112.33,3481.11 2115.46,3485.79 2120.13,3488.91 2125.65,3490.01 2131.17,3488.91 2135.85,3485.79 2138.97,3481.11 2140.07,3475.59 2138.97,3470.07 2135.85,3465.39 2135.65,3465.59 2136.04,3437.87 2134.49,3430.07 2130.07,3423.46 2129.79,3423.73 2107.79,3401.17 2101.17,3396.75 2093.37,3395.2 2093.37,3395.59 2042.94,3395.2 2035.13,3396.75 2028.52,3401.17 2028.79,3401.45 2024.65,3405.32 2019.1,3406.43 2014.33,3409.61 2011.14,3414.39 2010.02,3420.01 2011.14,3425.64 2014.33,3430.41 2019.1,3433.6 2024.73,3434.72 2030.36,3433.6 2035.13,3430.41 2038.32,3425.64 2039.42,3420.09 2039.15,3420.09 2040.59,3418.38 2043.89,3416.17 2047.79,3415.39 2047.79,3415.59 2089.51,3415.39 2093.41,3416.17 2096.72,3418.38 2096.58,3418.52 2112.86,3434.52 2115.07,3437.83 2115.85,3441.73 2115.65,3441.73 2115.65,3465.59
  region net VPROC_PMU: 1151.95,3896.49 1146.95,3901.49 1146.95,3973.49 1151.95,3978.49 1162.95,3978.49 1167.95,3973.49 1167.95,3901.49 1162.95,3896.49 1151.95,3896.49
  region net VBAT: 1057.31,2888.09 1139.31,2888.09 1139.31,2839.09 1057.31,2839.09 1057.31,2888.09
  region net VCORE_PMU: 1364.95,3283.83 1364.95,3211.83 1412.95,3211.83 1444.95,3243.83 1444.95,3283.83 1364.95,3283.83
  pour cut-out: 2129.65,3682.59 2180.37,3682.2 2188.17,3683.75 2194.79,3688.17 2194.51,3688.45 2313.62,3807.17 2318.67,3813.75 2321.84,3821.41 2322.92,3829.63 2322.65,3829.63 2323.05,3866.59 2321.52,3870.29 2321.24,3870 2288.75,3902.83 2283.09,3907.17 2276.51,3909.89 2269.44,3910.82 2269.44,3910.59 2250.66,3910.58 2249.11,3908.26 2243.46,3904.49 2236.79,3903.16 2230.12,3904.49 2224.46,3908.26 2220.68,3913.92 2219.36,3920.59 2220.68,3927.26 2224.46,3932.92 2230.12,3936.69 2236.79,3938.02 2243.46,3936.69 2249.11,3932.92 2250.66,3930.6 2250.65,3930.59 2269.09,3931 2281.42,3929.37 2292.91,3924.61 2302.78,3917.04 2302.49,3916.76 2332.42,3887.26 2338.14,3879.8 2341.73,3871.13 2342.96,3861.81 2342.65,3861.81 2343.06,3828.21 2341.43,3815.84 2336.66,3804.32 2329.07,3794.43 2328.78,3794.72 2208.61,3674.06 2200.26,3667.65 2190.53,3663.62 2180.08,3662.24 2180.08,3662.59 2106.65,3662.59 2098.73,3654.61 2099.55,3650.45 2098.47,3644.98 2095.37,3640.34 2090.73,3637.25 2085.27,3636.16 2079.8,3637.25 2075.16,3640.34 2072.07,3644.98 2070.98,3650.45 2072.07,3655.91 2075.16,3660.55 2079.4,3663.38 2079.48,3663.21 2089.84,3673.93 2096.07,3678.71 2103.33,3681.72 2111.12,3682.74 2111.12,3682.49 2129.65,3682.49 2129.65,3682.59
  region net VBAT: 1669.31,2847.56 1715.31,2893.56 1747.81,2861.06 1697.81,2811.06 1665.31,2843.56 1669.31,2843.56 1669.31,2847.56
  region net VBUS: 338.95,4625.83 392.95,4625.83 392.95,4575.83 338.95,4575.83 338.95,4625.83
  pour cut-out: 2120.65,3616.59 2130.65,3606.59 2130.52,3580.71 2127.77,3576.6 2126.71,3571.26 2127.77,3565.93 2130.79,3561.41 2135.32,3558.38 2140.65,3557.32 2145.99,3558.38 2150.51,3561.41 2153.53,3565.93 2154.59,3571.26 2153.53,3576.6 2150.78,3580.71 2150.65,3580.59 2150.98,3599.74 2149.67,3609.73 2145.81,3619.04 2139.68,3627.03 2139.44,3626.8 2135.66,3630.6 2136.21,3633.36 2134.9,3639.93 2131.18,3645.5 2125.61,3649.22 2119.04,3650.53 2112.47,3649.22 2106.9,3645.5 2103.17,3639.93 2101.87,3633.36 2103.17,3626.78 2106.9,3621.21 2112.47,3617.49 2119.04,3616.18 2120.66,3616.51 2120.65,3616.59
  pour cut-out: 970.76,4422.49 ccw(c957.95,4422.49) 957.95,4435.3 ccw(c957.95,4422.49) 945.14,4422.49 ccw(c957.95,4422.49) 957.95,4409.68 ccw(c957.95,4422.49)
Inner Layer 5:
  region net VBUS: 216.95,3759.83 243.95,3759.83 243.95,3724.83 216.95,3724.83 216.95,3759.83
  region net VBAT: 1435.31,3106.09 1435.31,3180.09 1502.31,3180.09 1507.31,3175.09 1507.31,3106.09 1435.31,3106.09
  region net VCORE_PMU: 1152.95,3758.49 1147.95,3763.49 1147.95,3849.49 1152.95,3854.49 1156.95,3854.49 1161.95,3849.49 1161.95,3763.49 1156.95,3758.49 1152.95,3758.49
  region net VBAT: 1686.31,2878.56 1743.31,2878.56 1743.31,2825.56 1686.31,2825.56 1686.31,2878.56
  region net VM_EXT: 647.95,3627.49 683.95,3627.49 694.45,3637.99 734.95,3637.99 734.95,3619.49 726.95,3611.49 647.95,3611.49 647.95,3627.49
  region net D_GND: 1253.95,3736.49 1248.95,3741.49 1248.95,3847.49 1253.95,3852.49 1260.95,3852.49 1265.95,3847.49 1265.95,3741.49 1260.95,3736.49 1253.95,3736.49
  region net D_GND: 1248.95,3697.49 1248.95,3750.49 1265.95,3750.49 1265.95,3711.49 1279.45,3697.99 1279.45,3684.49 1261.95,3684.49 1248.95,3697.49
  region net VBAT: 1055.31,2915.09 1132.31,2915.09 1132.31,2839.09 1055.31,2839.09 1055.31,2915.09
  region net VCORE_PMU: 1229.95,3736.49 1224.95,3741.49 1224.95,3828.49 1229.95,3833.49 1236.95,3833.49 1241.95,3828.49 1241.95,3741.49 1236.95,3736.49 1229.95,3736.49
  region net D_GND: 1169.95,3756.49 1169.95,3858.49 1174.95,3863.49 1195.95,3863.49 1195.95,3756.49 1169.95,3756.49
  region net D_GND: 1104.95,3915.49 1114.95,3905.49 1132.95,3905.49 1138.95,3911.49 1138.95,3991.49 1146.45,3998.99 1184.95,3998.99 1190.2,4004.24 1190.2,4013.49 1183.58,4020.12 1113.58,4020.12 1104.95,4011.49 1104.95,3915.49
  region net VBUS: 302.95,4599.83 315.95,4612.83 381.95,4612.83 381.95,4570.83 302.95,4570.83 302.95,4599.83
  region net VBUS: 2385.95,4460.49 2435.95,4460.49 2435.95,4399.49 2385.95,4399.49 2385.95,4460.49
  region net D_GND: 1253.95,3894.49 1248.95,3899.49 1248.95,3940.49 1253.95,3945.49 1258.95,3945.49 1263.95,3940.49 1263.95,3899.49 1258.95,3894.49 1253.95,3894.49
  region net VCC2_PA: 2008.31,4397.09 2035.31,4397.09 2035.31,4370.09 2080.31,4325.09 2092.18,4325.09 2092.18,4299.89 2061.51,4299.89 2008.31,4353.09 2008.31,4397.09
  pour cut-out: 2198.72,4090.56 2198.72,4081.13 2204.2,4080.04 2209.85,4076.26 2213.63,4070.6 2214.96,4063.93 2213.63,4057.25 2209.85,4051.59 2204.2,4047.81 2197.52,4046.49 2190.85,4047.81 2185.19,4051.59 2181.41,4057.25 2180.08,4063.93 2180.71,4067.1 2180.56,4090.39 2177.84,4094.47 2176.86,4099.39 2177.84,4104.31 2180.63,4108.48 2184.8,4111.26 2189.72,4112.24 2194.63,4111.26 2198.8,4108.48 2201.59,4104.31 2202.57,4099.39 2201.59,4094.47 2198.88,4090.41 2198.72,4090.56
  pour cut-out: 690.48,4382.49 ccw(c677.95,4382.49) 677.95,4395.02 ccw(c677.95,4382.49) 665.42,4382.49 ccw(c677.95,4382.49) 677.95,4369.96 ccw(c677.95,4382.49)
  pour cut-out: 970.76,4422.49 ccw(c957.95,4422.49) 957.95,4435.3 ccw(c957.95,4422.49) 945.14,4422.49 ccw(c957.95,4422.49) 957.95,4409.68 ccw(c957.95,4422.49)
Bottom:
  region net VPROC_PMU: 1147.95,3961.49 1173.95,3961.49 1173.95,3884.49 1147.95,3884.49 1147.95,3961.49
  region net D_GND: 1614.95,3688.15 1614.95,4169.49 1650.95,4169.49 1650.95,3688.15 1614.95,3688.15
  region net VM_EXT: 625.31,3558.09 625.31,3607.94 645.81,3628.44 709.31,3628.44 711.56,3626.19 711.56,3603.09 664.31,3603.09 658.31,3597.09 658.31,3558.09 625.31,3558.09
  region net D_GND: 1614.95,3315.49 1614.95,3660.65 1650.95,3660.65 1650.95,3315.49 1614.95,3315.49
  region net D_GND: 2080.95,4559.49 2080.95,4527.49 1870.95,4527.49 1870.95,4219.49 2048.95,4219.49 2048.95,4525.49 2080.95,4525.49 2080.95,4187.49 1838.95,4187.49 1838.95,4559.49 2080.95,4559.49
  region net VBAT: 945.31,3381.09 945.31,3451.09 922.81,3473.59 900.31,3473.59 878.56,3495.34 845.31,3495.34 845.31,3523.09 879.31,3523.09 900.81,3544.59 1082.31,3544.59 1106.31,3520.59 1106.31,3438.09 1079.31,3411.09 1079.31,3167.09 1100.31,3167.09 1100.31,3063.09 1099.31,3063.09 1099.31,2846.09 997.97,2846.09 979.31,2864.75 979.31,3381.09 945.31,3381.09
  region net N17960953: 1268.31,3395.34 1268.31,3500.09 1287.31,3519.09 1441.31,3519.09 1466.31,3494.09 1466.31,3444.09 1453.81,3431.59 1348.31,3431.59 1312.06,3395.34 1268.31,3395.34
  region net VPROC_PMU: 1222.31,3997.09 1241.31,3997.09 1241.31,3934.09 1246.81,3928.59 1246.81,3875.09 1216.31,3875.09 1216.31,3933.09 1222.31,3939.09 1222.31,3997.09
  region net VCORE_PMU: 1091.31,3724.09 1140.31,3724.09 1153.31,3737.09 1153.31,3758.09 1138.31,3773.09 1138.31,3871.09 1160.31,3871.09 1163.31,3868.09 1163.31,3800.09 1171.81,3793.59 1171.81,3771.59 1183.06,3760.34 1205.31,3760.34 1213.31,3768.34 1213.31,3792.09 1225.5,3804.28 1225.5,3864.09 1242.31,3864.09 1242.31,3769.09 1234.31,3761.09 1234.31,3699.09 1195.31,3699.09 1195.31,3628.09 1091.31,3628.09 1091.31,3724.09
  region net VBUS: 214.31,3761.09 518.31,3761.09 518.31,3707.09 214.31,3707.09 214.31,3761.09
  pour cut-out: 1368.95,3317.83 1368.95,3366.83 1395.45,3393.33 1416.95,3393.33 1429.7,3380.58 1429.7,3374.83 1425.95,3374.83 1425.95,3378.83 1416.45,3388.33 1397.95,3388.33 1380.2,3370.58 1380.2,3317.83 1368.95,3317.83
  region net ISENSE: 531.31,3752.09 590.31,3752.09 590.31,3463.09 634.31,3419.09 861.81,3419.09 876.06,3433.34 876.06,3450.09 918.31,3450.09 918.31,3392.09 887.31,3361.09 887.31,3344.09 872.31,3344.09 837.31,3379.09 602.31,3379.09 531.31,3450.09 531.31,3752.09
  region net VBAT: 1099.31,3167.09 1488.31,3167.09 1488.31,3112.09 1453.31,3112.09 1404.31,3063.09 1099.31,3063.09 1099.31,3167.09
  region net D_GND: 2292.62,3315.63 2292.62,4169.99 2328.38,4169.99 2328.38,3315.63 2292.62,3315.63
  region net DVDD_LTE: 1285.31,3811.09 1285.31,3979.09 1251.31,3979.09 1251.31,3996.09 1287.81,4032.59 1287.81,4066.09 1302.31,4066.09 1302.31,3986.09 1309.81,3978.59 1309.81,3953.09 1321.31,3953.09 1321.31,3811.09 1285.31,3811.09
  region net VCC2_PA: 1985.31,4396.09 1995.31,4396.09 1995.31,4427.09 2038.31,4427.09 2038.31,4373.09 2009.31,4373.09 2005.31,4377.09 1985.31,4377.09 1985.31,4396.09
  region net VBUS: 2402.95,4447.49 2436.95,4447.49 2436.95,4400.49 2402.95,4400.49 2402.95,4447.49
  region net D_GND: 1619.15,3759.59 2326.95,3759.59 2326.95,3723.59 1619.15,3723.59 1619.15,3759.59
  region net D_GND: 1613.95,3351.49 2327.95,3351.49 2327.95,3315.49 1613.95,3315.49 1613.95,3351.49
  region net VCC1_PA: 1983.31,4298.09 2037.31,4298.09 2037.31,4256.09 2018.31,4256.09 2018.31,4274.09 2011.31,4281.09 1983.31,4281.09 1983.31,4298.09
  region net D_GND: 1614.95,4169.99 2059.15,4169.99 2059.15,4133.99 1614.95,4133.99 1614.95,4169.99

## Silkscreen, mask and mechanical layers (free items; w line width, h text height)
Silkscreen Top:
  lines w10: 1719.65,3316.59 2417.65,3316.59 2417.65,4271.59 1719.65,4271.59 1719.65,3316.59
  text "6735 reference phone_V1" at 1377.28,714.42 h40
  text "WS2978" at 1649.31,572.09 h40
Silkscreen Bottom:
  lines w4: 181.31,4002.09 519.31,4002.09 519.31,4339.09 181.31,4339.09 181.31,4002.09 ; 187.31,3365.09 525.31,3365.09 525.31,3702.09 187.31,3702.09 187.31,3365.09
  lines w5: 1961.27,446.68 2468.27,446.68 2468.27,628.68 1961.27,628.68 1961.27,446.68
Solder Mask Top:
  region: 1509.67,5070.69 1592.67,5070.69 1592.67,5023.09 1509.67,5023.09 1509.67,5070.69
  region: 1972.95,4992.49 2127.95,4992.49 2127.95,4888.49 1972.95,4888.49 1972.95,4992.49
  region: 88.95,860.49 576.31,860.49 576.31,807.09 88.95,807.09 88.95,860.49
  region: 741.31,962.09 741.31,1542.09 770.31,1542.09 770.31,962.09 741.31,962.09
  region: 764.31,1513.09 441.95,1513.09 441.95,1542.09 764.31,1542.09 764.31,1513.09
Solder Mask Bottom:
  region: 940.3,767.09 1411.3,767.09 1411.3,597.09 940.3,597.09 940.3,767.09
  region: 1309.16,129.73 1427.26,129.73 1427.26,11.62 1309.16,11.62 1309.16,129.73
  region: 316.3,130.09 434.4,130.09 434.4,11.98 316.3,11.98 316.3,130.09
  region: 1321.31,4195.09 1321.31,4339.09 1362.31,4339.09 1362.31,4195.09 1321.31,4195.09
  region: 418.31,4007.5 418.31,4405.09 459.31,4405.09 459.31,4007.5 418.31,4007.5
  region: 417.31,4407.09 759.31,4407.09 759.31,4366.09 417.31,4366.09 417.31,4407.09
Layer_13 Mechanical-1:
  drawing of 3523 lines, arcs and shapes, not listed
  text "TOP VIEW" at 542.54,5814.5 h168.73
  text "MIC-2" at 751.29,5137.03 h42.18
  text "IRTX" at 505.26,5133.09 h42.18
  text "30" at 1537.01,5049.4 h28.12
  text "Sub CAM_conn" at 1633.94,5045.43 h22.5
  text "2" at 1928.56,5040.5 h28.12
  text "1" at 887.86,5036.7 h9.63
  text "1" at 627.28,4993.64 h14.06
  text "REC" at 1141.18,4989.84 h42.18
  text "+" at 625.02,4962.09 h14.06
  text "CAM" at 2056.82,4947.26 h42.18
  text "1" at 1931.06,4905.3 h28.12
  text "29" at 1536.73,4900.95 h28.12
  text "MT6158" at 1699.31,4288.78 h84.36
  text "MT6625" at 478.85,4127.77 h84.36
  text "H=1.5mm" at 1025.22,4114.54 h89.99
  text "Denali" at 1092.86,3755.47 h84.36
  text "eMCP" at 548.84,3748.42 h84.36
  text "MT6169" at 1737.98,3442.51 h84.36
  text "MT6328" at 982.75,3016.77 h84.36
  text "LCM_conn" at 833.46,2391.89 h42.18
  text "H=0.9mm" at 240.58,2342.01 h28.12
  text "T-Flash" at 140.99,1125.2 h42.18
  text "1" at 1781.59,37.88 h9.63
  text "MIC-1" at 1761.09,-114.36 h42.18
Layer_14 Mechanical-2:
  drawing of 5986 lines, arcs and shapes, not listed
  text "BOTTOM VIEW" at 2410.19,5798.19 h168.73
  text "PXS" at 1927.82,5503.31 h42.18
  text "C2K ANT" at 2992.96,5352.36 h84.36
  text "WBG" at 482.8,5180.72 h84.36
  text "DRX ANT" at 2993.53,5144.82 h84.36
  text "power" at 2184.98,4890.24 h42.18
  text "1" at 1574.86,4686.82 h28.12
  text "6" at 1762.41,4687.23 h28.12
  text "NSimSun|b0|i0|c134|p49;30" at 1044.45,4511.26 h9.84 r90
  text "NSimSun|b0|i0|c134|p49;1" at 1155.74,4506.2 h9.84 r90
  text "PXS_conn" at 1737.21,4477.88 h15.75
  text "RF" at 809.04,4457.89 h42.18
  text "MicroUSB2.0 (Bottom)" at 3327.04,4351.86 h42.18
  text "RF" at 2060.92,4287.64 h42.18
  text "NSimSun|b0|i0|c134|p49;15" at 1150.87,4217.1 h9.84 r90
  text "NSimSun|b0|i0|c134|p49;16" at 1039.58,4216.55 h9.84 r90
  text "Main CAM_conn" at 1216.87,4018.96 h22.5 r270
  text "FlashLED" at 546.33,3638.34 h42.18
  text "Batt_conn" at 1350.76,3576.98 h42.18
  text "RF" at 2343.96,3339.98 h42.18
  text "Audio jack" at 578.25,3205.83 h42.18
  text "1" at 718.45,2600.9 h28.12
  text "2" at 530.65,2599.97 h28.12
  text "NFC ANT" at 399.87,2447.3 h22.5
  text "40pin_debug" at 1257.28,2396.17 h42.18
  text "39" at 729.55,2200.56 h28.12
  text "40" at 552.25,2199.02 h28.12
  text "NFC ANT" at 393.6,2187.06 h22.5
  text "MicroSIM-1" at 1225.89,1823.51 h42.18
  text "MicroSIM-2" at 1218.83,1296.27 h42.18
  text "Vibrator" at 2435.1,859.32 h42.18
  text "TP conn" at 2019.26,821.28 h42.18
  text "+" at 2264.57,806.53 h28.12
  text "SPK" at 1259.13,763.65 h42.18
  text "1" at 1752.54,745.92 h28.12
  text "9" at 2006.18,746.21 h28.12
  text "2" at 1750.59,674.48 h28.12
  text "10" at 2032.67,671.09 h28.12
  text "Vibrator" at 611.1,555.15 h42.18
  text "+" at 423.43,406.73 h28.12 r180
  text "LTE ANT" at 485.27,-255.29 h84.36
Layer_15 Mechanical-3:
  drawing of 3603 lines, arcs and shapes, not listed
  text "TOP VIEW" at 542.96,5815.45 h168.73
  text "MIC-2" at 751.71,5137.98 h42.18
  text "30" at 1537.44,5050.34 h28.12
  text "Sub CAM_conn" at 1634.36,5046.37 h22.5
  text "2" at 1928.99,5041.45 h28.12
  text "1" at 888.28,5037.64 h9.63
  text "REC" at 1141.6,4990.78 h42.18
  text "CAM" at 2057.24,4948.21 h42.18
  text "1" at 1931.49,4906.25 h28.12
  text "29" at 1537.15,4901.9 h28.12
  text "MT6158" at 1699.74,4289.73 h84.36
  text "MT6625" at 479.27,4128.71 h84.36
  text "H=1.5mm" at 1025.64,4115.48 h89.99
  text "Denali" at 1093.28,3756.41 h84.36
  text "eMCP" at 549.27,3749.36 h84.36
  text "MT6169" at 1738.4,3443.46 h84.36
  text "MT6328" at 983.17,3017.72 h84.36
  text "LCM_conn" at 833.88,2392.84 h42.18
  text "H=0.9mm" at 241,2342.95 h28.12
  text "T-Flash" at 141.41,1126.15 h42.18
  text "1" at 1782.01,38.82 h9.63
  text "MIC-1" at 1761.52,-113.41 h42.18
Layer_16 Mechanical-4:
  drawing of 5936 lines, arcs and shapes, not listed
  text "BOTTOM VIEW" at 2411.92,5797.92 h168.73
  text "PXS" at 1929.56,5503.03 h42.18
  text "C2K ANT" at 2994.69,5352.09 h84.36
  text "WBG" at 484.53,5180.45 h84.36
  text "DRX ANT" at 2995.27,5144.54 h84.36
  text "power" at 2186.71,4889.97 h42.18
  text "6" at 1764.15,4686.95 h28.12
  text "1" at 1576.59,4686.54 h28.12
  text "NSimSun|b0|i0|c134|p49;30" at 1046.19,4510.99 h9.84 r90
  text "NSimSun|b0|i0|c134|p49;1" at 1157.48,4505.92 h9.84 r90
  text "PXS_conn" at 1738.94,4477.6 h15.75
  text "RF" at 810.78,4457.61 h42.18
  text "MicroUSB2.0 (Bottom)" at 3328.77,4351.58 h42.18
  text "RF" at 2062.65,4287.37 h42.18
  text "NSimSun|b0|i0|c134|p49;15" at 1152.61,4216.82 h9.84 r90
  text "NSimSun|b0|i0|c134|p49;16" at 1041.32,4216.27 h9.84 r90
  text "Main CAM_conn" at 1218.6,4018.69 h22.5 r270
  text "FlashLED" at 548.07,3638.06 h42.18
  text "Batt_conn" at 1352.49,3576.7 h42.18
  text "RF" at 2345.7,3339.7 h42.18
  text "Audio jack" at 579.99,3205.55 h42.18
  text "1" at 720.19,2600.62 h28.12
  text "2" at 532.39,2599.7 h28.12
  text "NFC ANT" at 401.6,2447.02 h22.5
  text "40pin_debug" at 1259.02,2395.89 h42.18
  text "39" at 731.29,2200.29 h28.12
  text "40" at 553.98,2198.74 h28.12
  text "NFC ANT" at 395.33,2186.78 h22.5
  text "MicroSIM-1" at 1227.63,1823.24 h42.18
  text "MicroSIM-2" at 1220.56,1295.99 h42.18
  text "Vibrator" at 2436.83,859.05 h42.18
  text "TP conn" at 2020.99,821 h42.18
  text "+" at 2266.31,806.25 h28.12
  text "SPK" at 1260.86,763.38 h42.18
  text "1" at 1754.27,745.64 h28.12
  text "9" at 2007.92,745.94 h28.12
  text "2" at 1752.32,674.2 h28.12
  text "10" at 2034.41,670.81 h28.12
  text "Vibrator" at 612.84,554.87 h42.18
  text "+" at 425.17,406.45 h28.12 r180
  text "LTE ANT" at 487.01,-255.57 h84.36
Limit:
  lines w4: 0,105.07 0,0 146.13,0
Drill Drawing:
  lines w1: 1291.22,5165.36 1291.25,5165.36 ; 1350.28,0 1350.3,0 ; 0,1147.77 0.03,1147.77 ; 2641.73,424.14 2641.76,424.14
  lines w10: -395,0 1300.28,0 ; -395,5165.36 1241.22,5165.36 ; -345,2515.18 -345,0 ; -345,2650.18 -345,5165.36 ; 0,-400 0,1097.77 ; 1120.41,-350 0,-350 ; 1521.32,-350 2641.73,-350 ; 2641.73,-400 2641.73,374.14 ; -345,0 -370,100 -320,100 -345,0 ; -345,5165.36 -320,5065.36 -370,5065.36 -345,5165.36 ; 0,-350 100,-325 100,-375 0,-350 ; 2641.73,-350 2541.73,-375 2541.73,-325 2641.73,-350
  text "131.20mm" at -532.5,2545.18 h50
  text "67.10mm" at 1150.41,-387.5 h50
